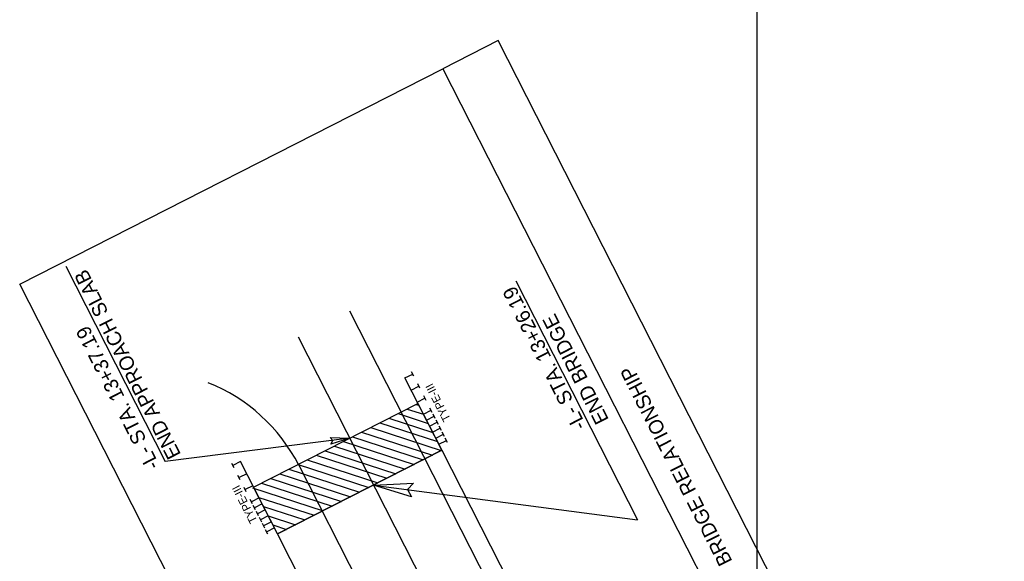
# Model space of a CAD drawing. Extents: x 557583 to 560285, y 513145 to 516544.
# Drawn here: x 558733.1 to 559074.2, y 516025.9 to 516213.5 of the extents above; entities that cross this region are included whole.
import ezdxf

# ---------------------------------------------------------------- set-up
doc = ezdxf.new("R2010")
doc.units = 0
for name, color, linetype in [('Default', 7, 'Continuous'), ('Exist Hydro Jurisdictional Stream or Body of Water NEU Mitigable Cogo Elevation', 7, 'Continuous'), ('Prop Approach Slab', 7, 'Continuous'), ('Prop Approach Slab Hatching', 7, 'Continuous'), ('Prop DSN Text', 7, 'Continuous'), ('Prop EOT', 7, 'Continuous'), ('Prop Roadway Bridge', 7, 'Continuous'), ('Prop Structure Anchor Unit CELL', 7, 'Continuous'), ('Prop Terminator CELL', 7, 'Continuous')]:
    doc.layers.add(name, color=color, linetype=linetype)

msp = doc.modelspace()

# ---------------------------------------------------------------- linework, layer by layer
at = {"layer": 'Default'}
msp.add_line((558988.6, 516003.66), (558988.6, 516457.65), dxfattribs=at)
at = {"layer": 'Exist Hydro Jurisdictional Stream or Body of Water NEU Mitigable Cogo Elevation'}
msp.add_line((558829.57, 516103.63), (558902.55, 515960.27), dxfattribs=at)
at = {"layer": 'Prop Approach Slab'}
for p, q in [((558814.13, 516051.59), (558871.05, 516080.57)), ((558871.05, 516080.57), (558879.31, 516064.35)), ((558879.31, 516064.35), (558822.39, 516035.37)), ((558822.39, 516035.37), (558814.13, 516051.59))]:
    msp.add_line(p, q, dxfattribs=at)
at = {"layer": 'Prop Approach Slab Hatching'}
for p, q in [((558870.46, 516080.27), (558871.36, 516079.97)), ((558864.16, 516077.06), (558874.57, 516073.67)), ((558867.31, 516078.66), (558872.96, 516076.82)), ((558857.85, 516073.85), (558877.77, 516067.37)), ((558861, 516075.45), (558876.17, 516070.52)), ((558851.55, 516070.64), (558876.03, 516062.68)), ((558854.7, 516072.25), (558879.38, 516064.22)), ((558845.25, 516067.43), (558869.73, 516059.47)), ((558848.4, 516069.04), (558872.88, 516061.08)), ((558838.95, 516064.23), (558863.43, 516056.26)), ((558842.1, 516065.83), (558866.58, 516057.87)), ((558829.5, 516059.41), (558853.98, 516051.45)), ((558832.65, 516061.02), (558857.13, 516053.06)), ((558835.8, 516062.62), (558860.28, 516054.66)), ((558823.2, 516056.21), (558847.68, 516048.24)), ((558826.35, 516057.81), (558850.83, 516049.85)), ((558816.9, 516053), (558841.38, 516045.03)), ((558820.05, 516054.6), (558844.53, 516046.64)), ((558813.74, 516051.39), (558838.22, 516043.43)), ((558815.94, 516048.05), (558835.07, 516041.83)), ((558817.54, 516044.9), (558831.92, 516040.22)), ((558819.21, 516041.62), (558828.64, 516038.55)), ((558820.8, 516038.49), (558825.51, 516036.96))]:
    msp.add_line(p, q, dxfattribs=at)
at = {"layer": 'Prop DSN Text'}
for p, q in [((558749.07, 516128.18), (558783.52, 516060.51)), ((558905, 516123.05), (558947.14, 516040.29)), ((558847.43, 516068.54), (558783.52, 516060.51)), ((558855.69, 516052.32), (558947.14, 516040.29))]:
    msp.add_line(p, q, dxfattribs=at)
for points in [[(558879.66, 516196.55), (559055, 515852.15), (559074.16, 515861.9), (558898.81, 516206.31)], [(558879.66, 516196.55), (559055, 515852.15), (558908.44, 515777.53), (558733.09, 516121.93)]]:
    msp.add_lwpolyline(points, close=True, dxfattribs=at)
at = {"layer": 'Prop EOT'}
for p, q in [((558847.39, 516112.7), (558920.38, 515969.34)), ((558829.76, 516059.17), (558884.73, 515951.19))]:
    msp.add_line(p, q, dxfattribs=at)
msp.add_arc((558776.29, 516031.95), 60, 26.9819, 68.41, dxfattribs=at)
at = {"layer": 'Prop Roadway Bridge'}
for p, q in [((558822.39, 516035.37), (558879.31, 516064.35)), ((558879.31, 516064.35), (558963.04, 515899.89)), ((558906.05, 515871.06), (558822.39, 516035.37))]:
    msp.add_line(p, q, dxfattribs=at)
at = {"layer": 'Prop Structure Anchor Unit CELL'}
for p, q in [((558866.55, 516089.41), (558869.22, 516090.77)), ((558869.61, 516090.01), (558868.84, 516091.54)), ((558879.31, 516064.35), (558866.55, 516089.41)), ((558868.68, 516085.24), (558871.35, 516086.6)), ((558871.74, 516085.83), (558870.96, 516087.36)), ((558873.87, 516081.65), (558873.09, 516083.19)), ((558870.81, 516081.06), (558873.48, 516082.42)), ((558872.93, 516076.88), (558875.61, 516078.24)), ((558876, 516077.48), (558875.22, 516079.01)), ((558877.06, 516075.39), (558876.28, 516076.92)), ((558874, 516074.79), (558876.67, 516076.15)), ((558875.06, 516072.7), (558877.73, 516074.07)), ((558878.12, 516073.3), (558877.34, 516074.83)), ((558876.12, 516070.62), (558878.8, 516071.98)), ((558877.19, 516068.53), (558879.86, 516069.89)), ((558879.19, 516071.21), (558878.41, 516072.74)), ((558880.25, 516069.12), (558879.47, 516070.65)), ((558878.25, 516066.44), (558880.92, 516067.8)), ((558881.31, 516067.03), (558880.53, 516068.56)), ((558807.35, 516058.31), (558806.57, 516059.84)), ((558809.63, 516060.43), (558806.96, 516059.07)), ((558822.39, 516035.37), (558809.63, 516060.43)), ((558811.76, 516056.26), (558809.09, 516054.9)), ((558809.48, 516054.13), (558808.7, 516055.66)), ((558811.6, 516049.95), (558810.82, 516051.48)), ((558813.89, 516052.08), (558811.21, 516050.72)), ((558813.73, 516045.78), (558812.95, 516047.31)), ((558816.01, 516047.9), (558813.34, 516046.54)), ((558817.08, 516045.81), (558814.4, 516044.45)), ((558814.79, 516043.69), (558814.01, 516045.22)), ((558815.86, 516041.6), (558815.08, 516043.13)), ((558818.14, 516043.72), (558815.47, 516042.36)), ((558816.92, 516039.51), (558816.14, 516041.04)), ((558819.2, 516041.64), (558816.53, 516040.28)), ((558817.98, 516037.42), (558817.2, 516038.95)), ((558820.27, 516039.55), (558817.59, 516038.19)), ((558819.05, 516035.33), (558818.27, 516036.86)), ((558821.33, 516037.46), (558818.66, 516036.1))]:
    msp.add_line(p, q, dxfattribs=at)
at = {"layer": 'Prop Terminator CELL'}
for points in [[(558840.59, 516068.85), (558847.43, 516068.54), (558840.85, 516066.5), (558841.55, 516067.8)], [(558868.77, 516048.26), (558855.69, 516052.32), (558869.46, 516052.94), (558867.44, 516050.78)]]:
    msp.add_lwpolyline(points, close=True, dxfattribs=at)

# ---------------------------------------------------------------- texts
at = {"layer": 'Prop DSN Text'}
for s, p in [('END APPROACH SLAB', (558789.06, 516062.9)), ('-L- STA. 13+26.19', (558929.48, 516072.84)), ('END BRIDGE', (558937.29, 516075)), ('-L- STA. 13+37.19', (558781.68, 516059.1)), ('DETAIL SHOWING PAVEMENT TO BRIDGE RELATIONSHIP', (559029.79, 515928.27))]:
    msp.add_text(s, height=5, rotation=116.9819, dxfattribs=at).set_placement(p)
at = {"layer": 'Prop Structure Anchor Unit CELL'}
for p in [(558882.46, 516075.19), (558815.49, 516039.92)]:
    msp.add_text('TYPE-III', height=2.812, rotation=116.9819, dxfattribs=at).set_placement(p)

doc.saveas('drawing.dxf')
